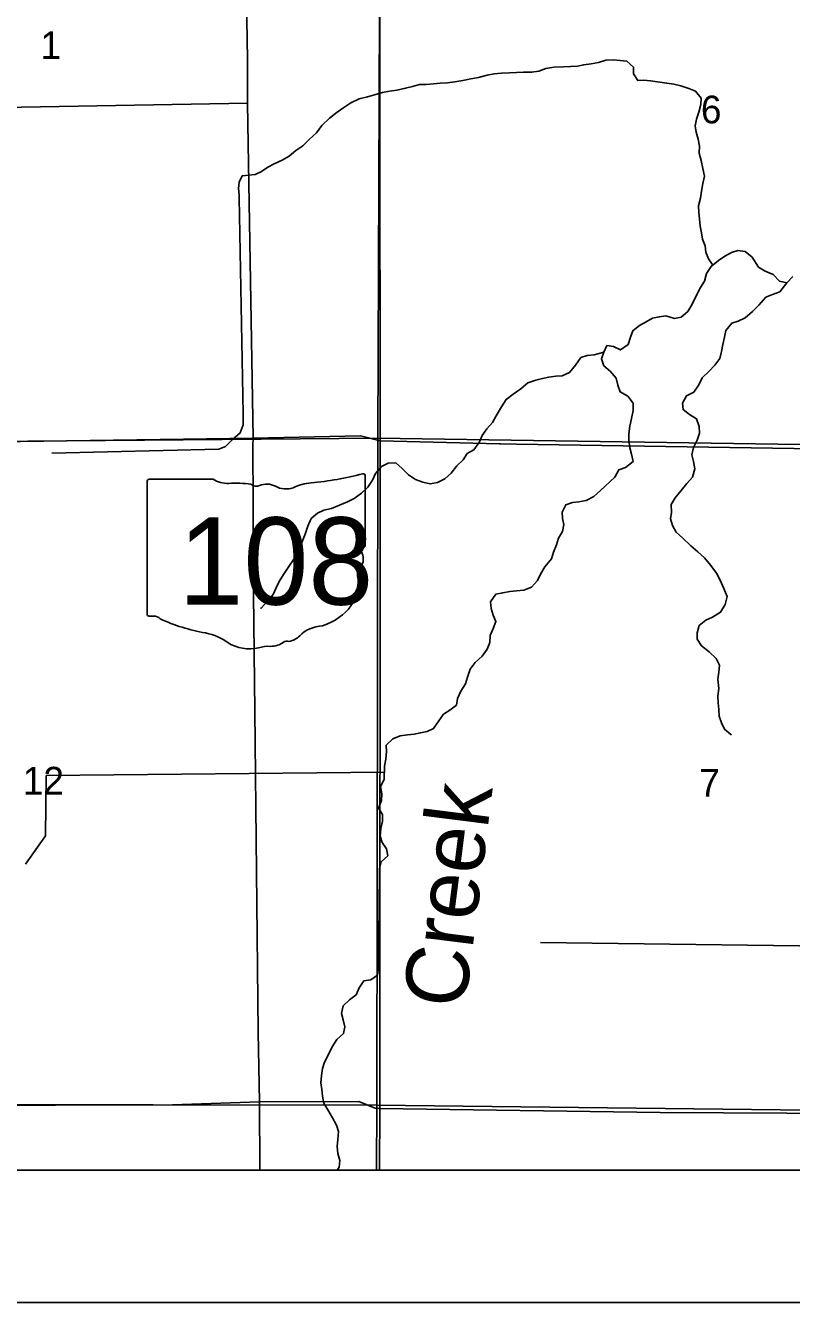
# Model space of a CAD drawing. Extents: x -6.2 to 37.4, y 0.2 to 22.2.
# Drawn here: x 2.605 to 3.183, y 14.207 to 15.172 of the extents above; entities that cross this region are included whole.
import ezdxf

# ---------------------------------------------------------------- set-up
doc = ezdxf.new("R2010")
doc.units = 0
for name, color, linetype in [('GM_X_County_Road', 7, 'Continuous'), ('GM_X_Minor_River', 7, 'Continuous'), ('GM_X_Minor_River_Text', 7, 'Continuous'), ('GM_X_Rail_Line', 7, 'Continuous'), ('GM_X_Section', 7, 'Continuous'), ('GM_X_Section_Text', 7, 'Continuous'), ('GM_X_State_Location', 7, 'Continuous'), ('GM_X_State_Route', 7, 'Continuous'), ('GM_X_State_Shield', 7, 'Continuous'), ('GM_X_Township_Road', 7, 'Continuous'), ('GM_X_US_Shield', 7, 'Continuous'), ('SH_Cut_Line', 7, 'Continuous'), ('SH_Data', 7, 'Continuous')]:
    doc.layers.add(name, color=color, linetype=linetype)

msp = doc.modelspace()

# ---------------------------------------------------------------- linework, layer by layer
at = {"layer": 'GM_X_County_Road'}
msp.add_line((2.37011, 14.85446), (2.77644, 14.86023), dxfattribs=at)
for points in [[(2.77644, 14.86023), (2.85755, 14.86184), (2.87257, 14.85805), (2.96271, 14.85601), (2.96369, 14.85599)], [(2.96369, 14.85599), (2.97556, 14.85572), (3.24948, 14.85135), (3.37374, 14.85018)], [(2.36187, 14.35565), (2.71571, 14.35673), (2.78123, 14.35883)], [(2.78123, 14.35883), (2.85639, 14.35929), (2.86877, 14.35406)]]:
    msp.add_lwpolyline(points, dxfattribs=at)
at = {"layer": 'GM_X_Minor_River'}
for points in [[(3.12376, 14.99084), (3.12045, 14.99562), (3.11851, 15.0006), (3.11809, 15.00536), (3.11596, 15.01035), (3.11535, 15.0153), (3.11436, 15.02027), (3.11377, 15.02578), (3.11316, 15.03055), (3.11293, 15.03567), (3.11443, 15.04151), (3.11535, 15.04661), (3.11628, 15.05246), (3.1174, 15.05812), (3.11625, 15.06385), (3.11491, 15.06977), (3.11356, 15.07531), (3.11372, 15.08081), (3.11274, 15.08596), (3.1112, 15.09131), (3.11039, 15.09608), (3.11149, 15.10117), (3.11316, 15.10625), (3.11485, 15.11208), (3.115, 15.11682), (3.1108, 15.12225), (3.10555, 15.1243), (3.09974, 15.12637), (3.09446, 15.12747), (3.08898, 15.1282), (3.0837, 15.12911), (3.07671, 15.13007), (3.0718, 15.13059), (3.06705, 15.13035), (3.06379, 15.13538), (3.06394, 15.14031), (3.05896, 15.14501), (3.05385, 15.14534), (3.04856, 15.14588), (3.04305, 15.14566), (3.03731, 15.14393), (3.03178, 15.14276), (3.02626, 15.14216), (3.02149, 15.14116), (3.01617, 15.14075), (3.01105, 15.14071), (3.00364, 15.14035), (2.99755, 15.13939), (2.99237, 15.13745), (2.98684, 15.13648), (2.98078, 15.13665), (2.97015, 15.1362), (2.96407, 15.13581), (2.95874, 15.1354), (2.95341, 15.13441), (2.9469, 15.13251), (2.94099, 15.13155), (2.93489, 15.13021), (2.92879, 15.12925), (2.92346, 15.12864), (2.91776, 15.12824), (2.91282, 15.12781), (2.9073, 15.12721), (2.90219, 15.12736), (2.89702, 15.1258), (2.89167, 15.12444), (2.88518, 15.12292), (2.87965, 15.12213), (2.87432, 15.12134), (2.8682, 15.11943), (2.86284, 15.11788), (2.85654, 15.11654), (2.85038, 15.11331), (2.84497, 15.10986), (2.83993, 15.1064), (2.8341, 15.10183), (2.82844, 15.0963), (2.82429, 15.09073), (2.81883, 15.08577), (2.81414, 15.08097), (2.80891, 15.07733), (2.80366, 15.07312), (2.79845, 15.07004), (2.79249, 15.06737), (2.78767, 15.06485), (2.78283, 15.06158), (2.77802, 15.05925), (2.77327, 15.05882), (2.76833, 15.05839), (2.76609, 15.05353), (2.76557, 15.04861), (2.76599, 15.04385), (2.76602, 15.04164)], [(2.76602, 15.04164), (2.76897, 14.87853), (2.76891, 14.87018), (2.76683, 14.86417), (2.761, 14.85922), (2.75553, 14.85388), (2.75072, 14.85174), (2.62435, 14.84896)], [(3.18432, 14.98219), (3.17963, 14.97739), (3.17417, 14.97869), (3.16939, 14.98376), (3.1634, 14.98621), (3.15837, 14.98939), (3.15348, 14.99693), (3.14811, 15.00126), (3.14263, 15.00199), (3.13785, 15.00042), (3.13284, 14.99772), (3.12799, 14.99426), (3.12255, 14.98986), (3.11897, 14.98447), (3.11748, 14.97882)], [(3.11748, 14.97882), (3.11449, 14.97397), (3.11147, 14.96818), (3.10802, 14.96088), (3.10503, 14.95584), (3.09997, 14.95163), (3.09482, 14.95064), (3.08824, 14.95254), (3.08348, 14.95192), (3.07833, 14.95074), (3.07332, 14.94804), (3.06849, 14.94533), (3.06344, 14.94131), (3.06159, 14.93643), (3.05972, 14.93098), (3.05409, 14.92678), (3.04886, 14.9294), (3.04377, 14.93011), (3.04153, 14.92506), (3.03967, 14.91999), (3.04141, 14.91482), (3.04621, 14.91069), (3.05079, 14.90544), (3.05216, 14.90028), (3.0539, 14.8951), (3.05949, 14.89191), (3.0635, 14.88648), (3.06352, 14.88116), (3.06239, 14.87513), (3.06108, 14.86928), (3.06034, 14.86342), (3.06037, 14.8583), (3.06115, 14.85278), (3.06233, 14.848), (3.06369, 14.84265), (3.05786, 14.83808), (3.05269, 14.83614), (3.04968, 14.83073), (3.03894, 14.8206), (3.03388, 14.8162), (3.0281, 14.81314), (3.02257, 14.81197), (3.01781, 14.81154), (3.01264, 14.8098), (3.01001, 14.80437), (3.01025, 14.79962), (3.01124, 14.79485), (3.01013, 14.78957), (3.00732, 14.78453), (3.00566, 14.77965), (3.00341, 14.77402), (3.00192, 14.76894), (2.997, 14.76302), (2.99361, 14.75742), (2.99138, 14.75256), (2.98687, 14.74757), (2.98093, 14.74546), (2.9756, 14.74486), (2.97047, 14.74444), (2.96513, 14.74346), (2.95978, 14.74228), (2.95582, 14.73652), (2.95624, 14.73158), (2.95798, 14.7264), (2.95991, 14.7216), (2.95786, 14.71635), (2.95562, 14.71111), (2.95527, 14.70581), (2.95341, 14.70074), (2.94946, 14.69554), (2.94438, 14.69076), (2.94044, 14.68575), (2.93855, 14.67974), (2.93688, 14.67467), (2.93349, 14.66907), (2.93104, 14.66345), (2.93013, 14.65855), (2.92509, 14.65471), (2.92025, 14.65163), (2.91688, 14.64661), (2.91291, 14.64084), (2.90792, 14.63871), (2.90296, 14.63772), (2.89818, 14.63653), (2.89324, 14.6361), (2.88752, 14.63532), (2.88215, 14.63301), (2.87707, 14.62823), (2.87731, 14.62348), (2.87675, 14.61761), (2.87584, 14.61252), (2.87553, 14.60229), (2.87271, 14.59706), (2.87368, 14.59153), (2.87353, 14.58641), (2.87127, 14.58079), (2.87416, 14.57596), (2.87419, 14.57084), (2.87289, 14.56538), (2.87253, 14.5597), (2.87409, 14.55491)], [(3.17963, 14.97739), (3.17431, 14.97072), (3.16893, 14.96859), (3.16394, 14.96665), (3.15864, 14.96055), (3.15376, 14.95575), (3.14811, 14.95099), (3.14292, 14.94848), (3.13814, 14.9471), (3.13361, 14.94154), (3.1327, 14.93645), (3.13139, 14.93098), (3.13028, 14.92551), (3.12899, 14.92043), (3.12524, 14.91542), (3.12091, 14.91042), (3.11584, 14.90563), (3.11322, 14.9004), (3.10945, 14.89501), (3.10386, 14.89213), (3.10085, 14.88653), (3.10128, 14.88177), (3.10609, 14.87803), (3.1115, 14.87484), (3.11359, 14.8689), (3.11363, 14.86396), (3.11196, 14.8587), (3.10932, 14.85309), (3.10802, 14.84762), (3.1092, 14.84266), (3.11017, 14.83713), (3.10846, 14.83073), (3.10414, 14.82592), (3.1, 14.82073), (3.09547, 14.81498), (3.09228, 14.80995), (3.09248, 14.80406), (3.09195, 14.79915), (3.09332, 14.79417), (3.09601, 14.78916), (3.10119, 14.78465), (3.10708, 14.77879), (3.11244, 14.77427), (3.11742, 14.76976), (3.12218, 14.76412), (3.12655, 14.75812), (3.12943, 14.75291), (3.13208, 14.74657), (3.13456, 14.74062), (3.13324, 14.73459), (3.12964, 14.72863), (3.12365, 14.72501), (3.11846, 14.72269), (3.11341, 14.71866), (3.11191, 14.71302), (3.11196, 14.70827), (3.11523, 14.70344), (3.12116, 14.6989), (3.12631, 14.69382), (3.12881, 14.68863), (3.12846, 14.68333), (3.12754, 14.67804), (3.12828, 14.67119), (3.12754, 14.66533), (3.12795, 14.6602), (3.12837, 14.65526), (3.1286, 14.65032), (3.13034, 14.64515), (3.13266, 14.64034), (3.13747, 14.6364), (3.13803, 14.6362)], [(3.04153, 14.92506), (3.03407, 14.923), (3.02894, 14.92258), (3.02415, 14.92101), (3.02018, 14.91524), (3.01547, 14.90988), (3.00989, 14.90719), (3.00514, 14.90695), (2.99982, 14.90635), (2.99504, 14.90516), (2.99007, 14.90397), (2.98395, 14.90207), (2.97869, 14.89748), (2.97307, 14.89328), (2.96764, 14.88945), (2.96425, 14.88386), (2.96025, 14.87695), (2.95745, 14.8721), (2.95313, 14.8673), (2.94957, 14.86228), (2.94752, 14.8574), (2.94336, 14.85127), (2.93834, 14.84857), (2.93516, 14.84373), (2.93029, 14.83931), (2.92614, 14.83374), (2.92127, 14.82952), (2.91588, 14.82664), (2.91016, 14.82567), (2.9047, 14.82697), (2.89926, 14.82883), (2.89387, 14.83241), (2.88908, 14.83729), (2.88428, 14.84141), (2.87859, 14.84139), (2.87358, 14.83888), (2.86887, 14.83351), (2.86663, 14.82845), (2.86325, 14.82324), (2.85837, 14.81864), (2.85294, 14.81462), (2.84775, 14.81212), (2.84179, 14.80945), (2.83565, 14.80716), (2.82992, 14.80581), (2.82511, 14.80348), (2.82025, 14.79945), (2.8178, 14.79364), (2.81572, 14.78763), (2.81325, 14.78125), (2.8104, 14.77489), (2.80738, 14.7689), (2.80341, 14.76314), (2.79944, 14.75718), (2.79625, 14.75197), (2.79383, 14.7471), (2.79159, 14.74205), (2.78745, 14.73705), (2.78256, 14.73188), (2.78198, 14.7317)], [(3.34588, 14.74397), (3.32314, 14.74444), (3.31537, 14.61303), (3.31378, 14.60435), (3.31006, 14.60028), (3.30551, 14.59397), (3.2986, 14.58506), (3.27984, 14.56038), (3.27774, 14.55362), (3.27651, 14.54436), (3.27687, 14.53752), (3.27748, 14.53257), (3.27585, 14.52882), (3.27354, 14.52775), (3.26767, 14.52792), (3.25136, 14.52783), (3.24736, 14.52719), (3.24579, 14.51927), (3.24566, 14.51491), (3.24602, 14.48304), (3.24322, 14.47838), (3.24034, 14.47732), (3.22836, 14.47615), (2.99352, 14.47918)], [(2.8757, 14.6079), (2.62021, 14.60534), (2.61958, 14.55984), (2.60456, 14.53848)], [(2.87409, 14.55491), (2.87735, 14.54989), (2.87833, 14.54474), (2.87326, 14.54014), (2.87198, 14.53525), (2.87187, 14.53165)], [(2.87187, 14.53165), (2.87121, 14.46017)], [(2.87121, 14.46017), (2.87047, 14.4545), (2.86544, 14.45105), (2.8601, 14.45025), (2.85672, 14.44504), (2.85448, 14.4398), (2.84943, 14.43596), (2.84455, 14.43136), (2.84324, 14.42571), (2.84461, 14.42093), (2.84578, 14.41559), (2.84468, 14.4105), (2.8398, 14.40609), (2.83622, 14.4005), (2.83378, 14.39507), (2.83037, 14.38891), (2.82889, 14.38403), (2.82817, 14.37893), (2.82762, 14.37325), (2.82841, 14.3683), (2.82883, 14.36317), (2.82999, 14.35782), (2.83306, 14.3528), (2.83649, 14.34683), (2.83954, 14.34143), (2.84111, 14.33664), (2.84054, 14.33059), (2.84, 14.32529), (2.8406, 14.31997), (2.84195, 14.31462), (2.84162, 14.3097), (2.84003, 14.30742)]]:
    msp.add_lwpolyline(points, dxfattribs=at)
at = {"layer": 'GM_X_Rail_Line'}
msp.add_lwpolyline([(1.68086, 15.3872), (1.68086, 14.30742), (2.87188, 14.30742), (2.87214, 14.35429), (2.87246, 14.85833), (2.87203, 15.37415), (2.76877, 15.37817), (2.37809, 15.37991), (2.37429, 15.37998), (2.20578, 15.38316), (2.06408, 15.38491)], close=True, dxfattribs=at)
msp.add_lwpolyline([(5.08086, 15.35073), (4.88144, 15.3529), (4.36796, 15.35921), (3.87127, 15.36568), (3.36537, 15.36831), (2.87203, 15.37415), (2.87246, 14.85833), (2.87214, 14.35429), (2.87188, 14.30742), (5.08086, 14.30742)], dxfattribs=at)
at = {"layer": 'GM_X_Section'}
for points in [[(2.37903, 15.38039), (2.8728, 15.37579), (2.87069, 14.86011), (2.3709, 14.8559)], [(3.36378, 15.37031), (3.37458, 15.37032), (3.37432, 14.85252), (2.87069, 14.86011), (2.8728, 15.37579)], [(2.87069, 14.86011), (2.86992, 14.35634), (2.36268, 14.35718), (2.3709, 14.8559)], [(3.37432, 14.85252), (3.37093, 14.35069), (2.86992, 14.35634), (2.87069, 14.86011)]]:
    msp.add_lwpolyline(points, close=True, dxfattribs=at)
at = {"layer": 'GM_X_State_Route'}
for points in [[(2.77644, 14.86023), (2.77285, 15.08257), (2.77238, 15.11306), (2.77238, 15.1461), (2.77005, 15.28352), (2.76889, 15.37789)], [(2.78171, 14.30742), (2.78123, 14.35883), (2.78033, 14.41143), (2.77779, 14.65414), (2.77675, 14.74202), (2.77657, 14.80983), (2.77634, 14.85451), (2.77644, 14.86023)]]:
    msp.add_lwpolyline(points, dxfattribs=at)
at = {"layer": 'GM_X_State_Shield'}
for p, q in [((2.69641, 14.82743), (2.69641, 14.72737)), ((2.74629, 14.82916), (2.69803, 14.82916)), ((2.8612, 14.77929), (2.8612, 14.83163)), ((2.86119, 14.77931), (2.8612, 14.77929))]:
    msp.add_line(p, q, dxfattribs=at)
for centre, major_axis, start_param, end_param in [((2.8025, 14.96557), (0.17476, 0), 4.814394, 5.042369), ((2.85937, 14.83185), (0.00183, 0), 6.141152, 7.989035), ((2.6983, 14.82765), (0.00191, 0), 1.712693, 3.28349), ((2.75779, 14.84077), (0.01852, 0), 4.042523, 4.731795), ((2.76393, 14.77298), (0.06648, 0), 1.404758, 1.657858), ((2.77902, 14.82817), (0.00534, 0), 3.836095, 5.185415), ((2.78686, 14.8166), (0.01111, 0), 0.950623, 2.079405), ((2.80119, 14.83246), (0.01336, 0), 4.081561, 5.145723), ((2.82479, 14.79859), (0.03516, 0), 1.699011, 2.107814), ((2.86078, 14.77545), (0.00284, 0), 1.883978, 3.671073), ((2.84272, 14.76883), (0.01704, 0), 5.934695, 6.695948), ((2.85924, 14.77909), (0.00196, 0), 5.05454, 6.418171), ((2.81229, 14.75073), (0.04371, 0), 5.101752, 6.440018), ((2.86777, 14.75739), (0.0124, 0), 2.387724, 3.262537), ((2.69832, 14.72715), (0.00193, 0), 3.00124, 4.508301), ((2.69861, 14.73739), (0.0147, 0), 4.665946, 4.897461), ((2.70161, 14.7216), (0.0053, 0), 0.519207, 1.627899), ((2.76853, 14.8115), (0.1262, 0), 4.195997, 4.488961), ((2.83072, 14.69928), (0.02394, 0), 1.647645, 2.488434), ((2.7309, 14.68242), (0.03949, 0), 0.823519, 1.323587), ((2.80199, 14.70392), (0.00376, 0), 1.147584, 2.315152), ((2.80039, 14.71768), (0.01412, 0), 4.937069, 5.64225), ((2.77361, 14.7211), (0.02506, 0), 4.026481, 4.996735), ((2.78809, 14.68651), (0.02059, 0), 1.495662, 1.94098), ((2.78992, 14.71361), (0.01335, 0), 4.691044, 5.507374)]:
    msp.add_ellipse(centre, major_axis=major_axis, ratio=0.8, start_param=start_param, end_param=end_param, dxfattribs=at)
at = {"layer": 'GM_X_Township_Road'}
for points in [[(2.24231, 15.10557), (2.37392, 15.10601), (2.77238, 15.11306)], [(2.86877, 14.35406), (2.87225, 14.35401), (3.08408, 14.35099), (3.37112, 14.34926), (3.62115, 14.34388), (3.86853, 14.34513), (4.11685, 14.33933), (4.37144, 14.33706), (4.64671, 14.33435), (4.79438, 14.3344)]]:
    msp.add_lwpolyline(points, dxfattribs=at)
at = {"layer": 'GM_X_US_Shield'}
for points in [[(2.36241, 14.30742), (2.86967, 14.30742), (2.86992, 14.35634), (2.36268, 14.35718)], [(2.86967, 14.30742), (3.37083, 14.30742), (3.37093, 14.35069), (2.86992, 14.35634)]]:
    msp.add_lwpolyline(points, close=True, dxfattribs=at)
at = {"layer": 'SH_Cut_Line'}
msp.add_lwpolyline([(1.68086, 20.39726), (1.68086, 14.30742), (5.08086, 14.30742)], dxfattribs=at)
at = {"layer": 'SH_Data'}
for p, q in [((1.68086, 14.30742), (8.48086, 14.30742)), ((1.58086, 14.20742), (8.58086, 14.20742))]:
    msp.add_line(p, q, dxfattribs=at)

# ---------------------------------------------------------------- texts
at = {"layer": 'GM_X_Minor_River_Text'}
msp.add_text('Creek', height=0.047361, rotation=82.81871, dxfattribs=at).set_placement((2.93647, 14.42832))
at = {"layer": 'GM_X_Section_Text'}
for s, height, p in [('1', 0.02093, (2.61582, 15.14646)), ('6', 0.02093, (3.11477, 15.09792)), ('12', 0.020928, (2.60248, 14.59099)), ('7', 0.02093, (3.11352, 14.58943))]:
    msp.add_text(s, height=height, rotation=0.00001, dxfattribs=at).set_placement(p)
at = {"layer": 'GM_X_State_Location'}
for s, p in [('s', (2.77696, 14.77075)), ('r', (2.77695, 14.77075))]:
    msp.add_text(s, height=0.0000947, dxfattribs=at).set_placement(p)
msp.add_text('108', height=0.0000947, rotation=0.00001, dxfattribs=at).set_placement((2.74352, 14.76386))
at = {"layer": 'GM_X_State_Shield'}
msp.add_text('108', height=0.065918, dxfattribs=at).set_placement((2.72022, 14.73443))

doc.saveas('drawing.dxf')
